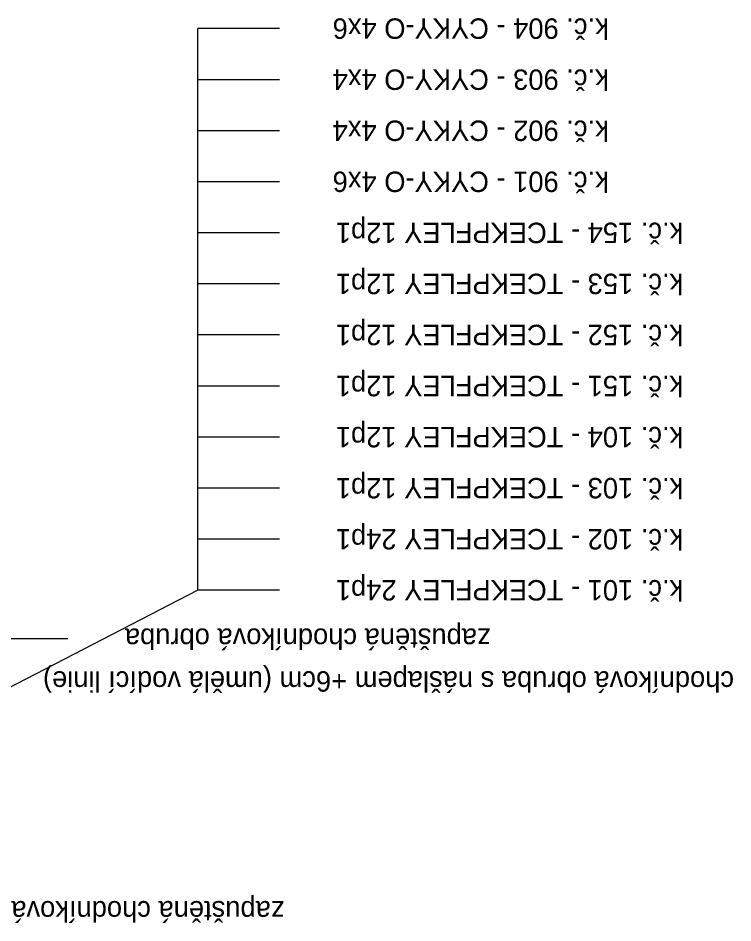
# Model space of a CAD drawing. Extents: x -728547 to -728179, y -1073068 to -1072839.
# Drawn here: x -728484.26 to -728466.75, y -1073041.14 to -1073018.99 of the extents above; entities that cross this region are included whole.
import ezdxf

# ---------------------------------------------------------------- set-up
doc = ezdxf.new("R2010")
doc.units = 0
doc.layers.add('_NOR-popis', color=7, linetype='Continuous')
doc.layers.add('KOS_kabelová trasa popis', color=7, linetype='Continuous')

msp = doc.modelspace()

# ---------------------------------------------------------------- linework, layer by layer
at = {"layer": '_NOR-popis'}
msp.add_line((-728483.044, -1073034.178), (-728485.044, -1073034.178), dxfattribs=at)
at = {"layer": 'KOS_kabelová trasa popis'}
for p, q in [((-728479.858, -1073032.993), (-728479.858, -1073019.243)), ((-728477.858, -1073019.243), (-728479.858, -1073019.243)), ((-728477.858, -1073020.493), (-728479.858, -1073020.493)), ((-728477.858, -1073021.743), (-728479.858, -1073021.743)), ((-728477.858, -1073022.993), (-728479.858, -1073022.993)), ((-728477.858, -1073024.243), (-728479.858, -1073024.243)), ((-728477.858, -1073025.493), (-728479.858, -1073025.493)), ((-728477.858, -1073026.743), (-728479.858, -1073026.743)), ((-728477.858, -1073027.993), (-728479.858, -1073027.993)), ((-728477.858, -1073029.243), (-728479.858, -1073029.243)), ((-728477.858, -1073030.493), (-728479.858, -1073030.493)), ((-728477.858, -1073031.743), (-728479.858, -1073031.743)), ((-728479.858, -1073032.993), (-728491.268, -1073038.884)), ((-728477.858, -1073032.993), (-728479.858, -1073032.993))]:
    msp.add_line(p, q, dxfattribs=at)

# ---------------------------------------------------------------- texts
at = {"layer": '_NOR-popis'}
for s, p in [('zapuštěná chodníková obruba', (-728472.686, -1073033.928)), ('chodníková obruba s nášlapem +6cm (umělá vodící linie)', (-728466.723, -1073034.975)), ('zapuštěná chodníková obruba', (-728477.736, -1073040.601))]:
    msp.add_text(s, height=0.5, rotation=180, dxfattribs=at).set_placement(p)
at = {"layer": 'KOS_kabelová trasa popis'}
for s, p in [('k.č. 904 - CYKY-O 4x6', (-728469.792, -1073018.993)), ('k.č. 903 - CYKY-O 4x4', (-728469.792, -1073020.243)), ('k.č. 902 - CYKY-O 4x4', (-728469.792, -1073021.493)), ('k.č. 901 - CYKY-O 4x6', (-728469.792, -1073022.743)), ('k.č. 154 - TCEKPFLEY 12p1', (-728467.967, -1073023.993)), ('k.č. 153 - TCEKPFLEY 12p1', (-728467.967, -1073025.243)), ('k.č. 152 - TCEKPFLEY 12p1', (-728467.967, -1073026.493)), ('k.č. 151 - TCEKPFLEY 12p1', (-728467.967, -1073027.743)), ('k.č. 104 - TCEKPFLEY 12p1', (-728467.967, -1073028.993)), ('k.č. 103 - TCEKPFLEY 12p1', (-728467.967, -1073030.243)), ('k.č. 102 - TCEKPFLEY 24p1', (-728467.967, -1073031.493)), ('k.č. 101 - TCEKPFLEY 24p1', (-728467.967, -1073032.743))]:
    msp.add_text(s, height=0.5, rotation=180, dxfattribs=at).set_placement(p)

doc.saveas('drawing.dxf')
